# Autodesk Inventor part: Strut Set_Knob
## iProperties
Shininess: 64.0
Length Units: 11272
Angle Units: 11279
Time Units: 11290
Mass Units: 11283
Length Display Precision: 3
Angle Display Precision: 2
Compacted: True
Part Number: Strut Set_Knob
Document SubType Name: Modeling
Created: 2005-03
Designer: Admin
Manufacturer: Standard
Standards Organization: Custom
Density: 1 g/cm^3
Density: 0.0
Volumn: 0.0
Area: 0.0
PropertySet Name: Model Information
Control State: 0
Master: False
Checked Out: False
Author: Admin
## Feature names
1. ExtrusionBlind1
2. ExtrusionBlind2
3. Hole1
4. RevolutionFull1
5. Chamfer1
6. RevolutionFull2
7. Fillet1
8. ExtrusionThru1
9. PolarArray1 [Circular Pattern]
